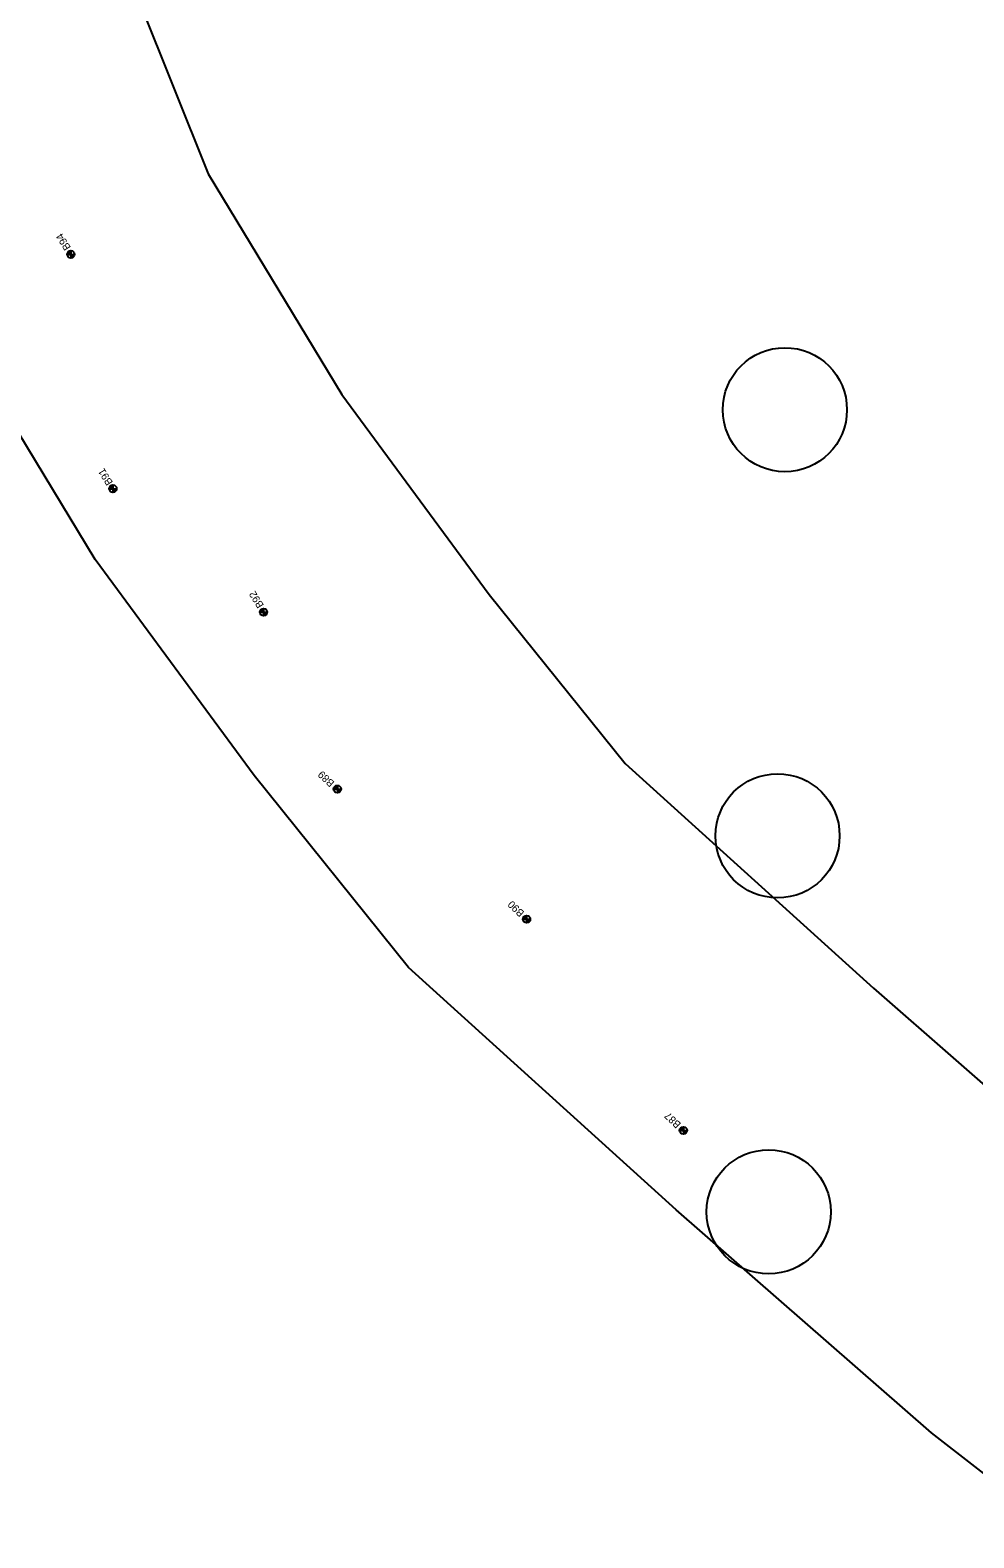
# Model space of a CAD drawing. Extents: x 327762 to 372792, y 127949 to 259367.
# Drawn here: x 356501 to 357773, y 178093 to 180127 of the extents above; entities that cross this region are included whole.
import ezdxf

# ---------------------------------------------------------------- set-up
doc = ezdxf.new("R2010")
doc.units = 0
for name, color, linetype in [('CE-TOPO-CONC-SLAB', 7, 'Continuous'), ('E_SOIL_BORE1 [KAPUR_CADDS_LEVELS]', 7, 'Continuous'), ('E_SOIL_BORE2 [KAPUR_CADDS_LEVELS]', 7, 'Continuous'), ('P_MARK', 7, 'Continuous'), ('P_TC', 7, 'Continuous')]:
    doc.layers.add(name, color=color, linetype=linetype)

msp = doc.modelspace()

# ---------------------------------------------------------------- linework, layer by layer
at = {"layer": 'CE-TOPO-CONC-SLAB'}
for centre in [(357518.5, 179614.5), (357508.6, 179039.7), (357496.7, 178532.5)]:
    msp.add_circle(centre, 83.7, dxfattribs=at)
at = {"layer": 'P_MARK'}
for p, q in [((356555.7, 179829.1), (356555.7, 179819.1)), ((356550.7, 179824.1), (356560.7, 179824.1)), ((356607.4, 179508), (356617.4, 179508)), ((356612.4, 179513), (356612.4, 179503)), ((356810.5, 179341.5), (356820.5, 179341.5)), ((356815.5, 179346.5), (356815.5, 179336.5)), ((356910, 179102.8), (356920, 179102.8)), ((356915, 179107.8), (356915, 179097.8)), ((357165.2, 178927.2), (357175.2, 178927.2)), ((357170.2, 178932.2), (357170.2, 178922.2)), ((357376.6, 178642.3), (357386.6, 178642.3)), ((357381.6, 178647.3), (357381.6, 178637.3))]:
    msp.add_line(p, q, dxfattribs=at)
for centre in [(356555.7, 179824.1), (356612.4, 179508), (356815.5, 179341.5), (356915, 179102.8), (357170.2, 178927.2), (357381.6, 178642.3)]:
    msp.add_circle(centre, 5, dxfattribs=at)
for centre, radius, start, end in [((356555.7, 179824.1), 4.5, 89.9869, 179.9869), ((356555.7, 179824.1), 4, 89.9869, 179.9869), ((356555.7, 179824.1), 3.5, 89.9869, 179.9869), ((356555.7, 179824.1), 3, 89.9869, 179.9869), ((356555.7, 179824.1), 2.5, 89.9869, 179.9869), ((356555.7, 179824.1), 2, 89.9869, 179.9869), ((356555.7, 179824.1), 1.5, 89.9869, 179.9869), ((356555.7, 179824.1), 1, 89.9869, 179.9869), ((356555.7, 179824.1), 0.5, 89.9869, 179.9869), ((356555.7, 179824.1), 4.5, 269.9869, 359.9869), ((356555.7, 179824.1), 4, 269.9869, 359.9869), ((356555.7, 179824.1), 3.5, 269.9869, 359.9869), ((356555.7, 179824.1), 3, 269.9869, 359.9869), ((356555.7, 179824.1), 2.5, 269.9869, 359.9869), ((356555.7, 179824.1), 2, 269.9869, 359.9869), ((356555.7, 179824.1), 1.5, 269.9869, 359.9869), ((356555.7, 179824.1), 1, 269.9869, 359.9869), ((356555.7, 179824.1), 0.5, 269.9869, 359.9869), ((356612.4, 179508), 4.5, 89.9869, 179.9869), ((356612.4, 179508), 4, 89.9869, 179.9869), ((356612.4, 179508), 3.5, 89.9869, 179.9869), ((356612.4, 179508), 3, 89.9869, 179.9869), ((356612.4, 179508), 2.5, 89.9869, 179.9869), ((356612.4, 179508), 2, 89.9869, 179.9869), ((356612.4, 179508), 1.5, 89.9869, 179.9869), ((356612.4, 179508), 1, 89.9869, 179.9869), ((356612.4, 179508), 0.5, 89.9869, 179.9869), ((356612.4, 179508), 4.5, 269.9869, 359.9869), ((356612.4, 179508), 4, 269.9869, 359.9869), ((356612.4, 179508), 3.5, 269.9869, 359.9869), ((356612.4, 179508), 3, 269.9869, 359.9869), ((356612.4, 179508), 2.5, 269.9869, 359.9869), ((356612.4, 179508), 2, 269.9869, 359.9869), ((356612.4, 179508), 1.5, 269.9869, 359.9869), ((356612.4, 179508), 1, 269.9869, 359.9869), ((356612.4, 179508), 0.5, 269.9869, 359.9869), ((356815.5, 179341.5), 4.5, 89.9869, 179.9869), ((356815.5, 179341.5), 4, 89.9869, 179.9869), ((356815.5, 179341.5), 3.5, 89.9869, 179.9869), ((356815.5, 179341.5), 3, 89.9869, 179.9869), ((356815.5, 179341.5), 2.5, 89.9869, 179.9869), ((356815.5, 179341.5), 2, 89.9869, 179.9869), ((356815.5, 179341.5), 1.5, 89.9869, 179.9869), ((356815.5, 179341.5), 1, 89.9869, 179.9869), ((356815.5, 179341.5), 0.5, 89.9869, 179.9869), ((356815.5, 179341.5), 4.5, 269.9869, 359.9869), ((356815.5, 179341.5), 4, 269.9869, 359.9869), ((356815.5, 179341.5), 3.5, 269.9869, 359.9869), ((356815.5, 179341.5), 3, 269.9869, 359.9869), ((356815.5, 179341.5), 2.5, 269.9869, 359.9869), ((356815.5, 179341.5), 2, 269.9869, 359.9869), ((356815.5, 179341.5), 1.5, 269.9869, 359.9869), ((356815.5, 179341.5), 1, 269.9869, 359.9869), ((356815.5, 179341.5), 0.5, 269.9869, 359.9869), ((356915, 179102.8), 4.5, 89.9869, 179.9869), ((356915, 179102.8), 4, 89.9869, 179.9869), ((356915, 179102.8), 3.5, 89.9869, 179.9869), ((356915, 179102.8), 3, 89.9869, 179.9869), ((356915, 179102.8), 2.5, 89.9869, 179.9869), ((356915, 179102.8), 2, 89.9869, 179.9869), ((356915, 179102.8), 1.5, 89.9869, 179.9869), ((356915, 179102.8), 1, 89.9869, 179.9869), ((356915, 179102.8), 0.5, 89.9869, 179.9869), ((356915, 179102.8), 4.5, 269.9869, 359.9869), ((356915, 179102.8), 4, 269.9869, 359.9869), ((356915, 179102.8), 3.5, 269.9869, 359.9869), ((356915, 179102.8), 3, 269.9869, 359.9869), ((356915, 179102.8), 2.5, 269.9869, 359.9869), ((356915, 179102.8), 2, 269.9869, 359.9869), ((356915, 179102.8), 1.5, 269.9869, 359.9869), ((356915, 179102.8), 1, 269.9869, 359.9869), ((356915, 179102.8), 0.5, 269.9869, 359.9869), ((357170.2, 178927.2), 4.5, 89.9869, 179.9869), ((357170.2, 178927.2), 4, 89.9869, 179.9869), ((357170.2, 178927.2), 3.5, 89.9869, 179.9869), ((357170.2, 178927.2), 3, 89.9869, 179.9869), ((357170.2, 178927.2), 2.5, 89.9869, 179.9869), ((357170.2, 178927.2), 2, 89.9869, 179.9869), ((357170.2, 178927.2), 1.5, 89.9869, 179.9869), ((357170.2, 178927.2), 1, 89.9869, 179.9869), ((357170.2, 178927.2), 0.5, 89.9869, 179.9869), ((357170.2, 178927.2), 4.5, 269.9869, 359.9869), ((357170.2, 178927.2), 4, 269.9869, 359.9869), ((357170.2, 178927.2), 3.5, 269.9869, 359.9869), ((357170.2, 178927.2), 3, 269.9869, 359.9869), ((357170.2, 178927.2), 2.5, 269.9869, 359.9869), ((357170.2, 178927.2), 2, 269.9869, 359.9869), ((357170.2, 178927.2), 1.5, 269.9869, 359.9869), ((357170.2, 178927.2), 1, 269.9869, 359.9869), ((357170.2, 178927.2), 0.5, 269.9869, 359.9869), ((357381.6, 178642.3), 4.5, 89.9869, 179.9869), ((357381.6, 178642.3), 4, 89.9869, 179.9869), ((357381.6, 178642.3), 3.5, 89.9869, 179.9869), ((357381.6, 178642.3), 3, 89.9869, 179.9869), ((357381.6, 178642.3), 2.5, 89.9869, 179.9869), ((357381.6, 178642.3), 2, 89.9869, 179.9869), ((357381.6, 178642.3), 1.5, 89.9869, 179.9869), ((357381.6, 178642.3), 1, 89.9869, 179.9869), ((357381.6, 178642.3), 0.5, 89.9869, 179.9869), ((357381.6, 178642.3), 4.5, 269.9869, 359.9869), ((357381.6, 178642.3), 4, 269.9869, 359.9869), ((357381.6, 178642.3), 3.5, 269.9869, 359.9869), ((357381.6, 178642.3), 3, 269.9869, 359.9869), ((357381.6, 178642.3), 2.5, 269.9869, 359.9869), ((357381.6, 178642.3), 2, 269.9869, 359.9869), ((357381.6, 178642.3), 1.5, 269.9869, 359.9869), ((357381.6, 178642.3), 1, 269.9869, 359.9869), ((357381.6, 178642.3), 0.5, 269.9869, 359.9869)]:
    msp.add_arc(centre, radius, start, end, dxfattribs=at)
at = {"layer": 'P_TC'}
for points in [[(356010.7, 184791.4), (356404.2, 181123.3), (356466.9, 180787.9), (356513.6, 180550.2), (356602.1, 180279.7), (356741, 179932.9), (356921, 179635), (357119.9, 179365.3), (357302.9, 179137.3), (357638, 178834.1), (357970.9, 178543), (358585.9, 178064.8), (358972.8, 177765.7), (359287.4, 177446.4), (359568.2, 177108.6), (359781.6, 176804.9), (359973.6, 176484.4), (360151.9, 176070.5), (360266.6, 175727.9), (360318.3, 175542.9)], [(359933.1, 175435.2), (359884.1, 175610.5), (359777.9, 175927.7), (359616.8, 176301.7), (359446, 176586.9), (359250.3, 176865.3), (358990.6, 177177.7), (358706.9, 177465.7), (358340.8, 177748.6), (357716.2, 178234.3), (357372.1, 178535.2), (357010.9, 178862.1), (356802.9, 179121.3), (356588.2, 179412.3), (356381.8, 179753.9), (356226, 180143), (356125.8, 180449.1), (356074, 180712.7), (356008.1, 181065.2), (355612.9, 184748.7)]]:
    msp.add_lwpolyline(points, dxfattribs=at)

# ---------------------------------------------------------------- texts
at = {"layer": 'E_SOIL_BORE1 [KAPUR_CADDS_LEVELS]'}
for s, p in [('B89', (356911.8, 179111.8)), ('B90', (357167.8, 178936.6)), ('B87', (357379.1, 178651.4))]:
    msp.add_text(s, height=10, rotation=136.1942, dxfattribs=at).set_placement(p)
at = {"layer": 'E_SOIL_BORE2 [KAPUR_CADDS_LEVELS]'}
for s, p in [('B94', (356556, 179833.4)), ('B91', (356612.7, 179516.4)), ('B92', (356816.3, 179350.8))]:
    msp.add_text(s, height=10, rotation=121.7799, dxfattribs=at).set_placement(p)

doc.saveas('drawing.dxf')
